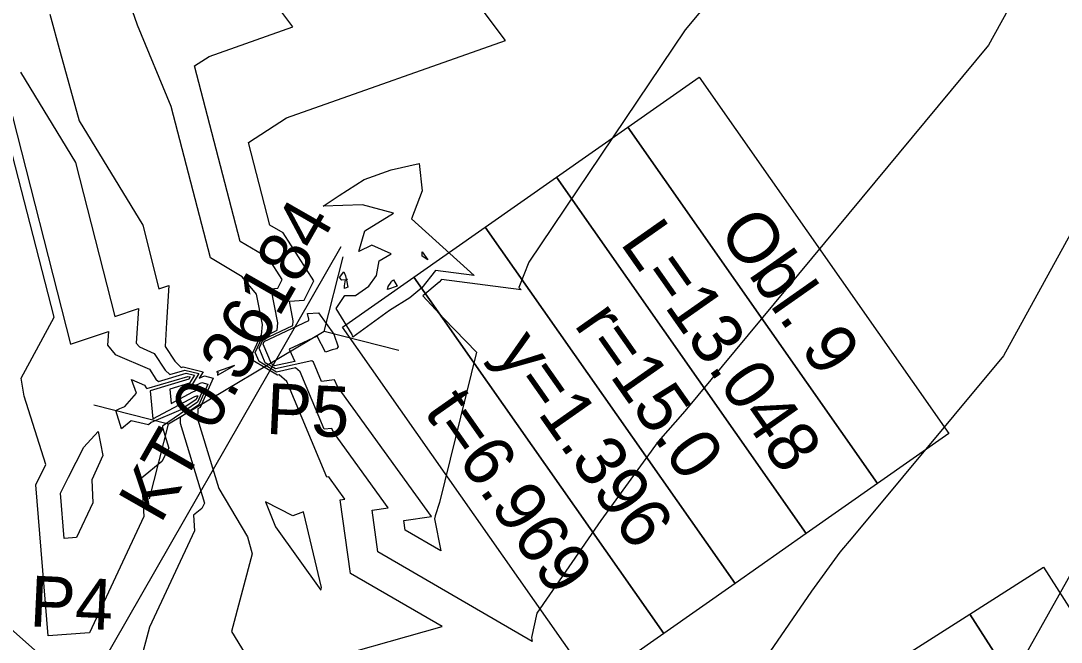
# Model space of a CAD drawing. Extents: x -549394 to -546608, y -1037055 to -1033629.
# Drawn here: x -547879.1 to -547807.4, y -1034621 to -1034578.2 of the extents above; entities that cross this region are included whole.
import ezdxf

# ---------------------------------------------------------------- set-up
doc = ezdxf.new("R2010")
doc.units = 0
for name, color, linetype in [('hlavni_vrst', 7, 'Continuous'), ('norm_vrst', 7, 'Continuous'), ('x_navrh_C21', 7, 'Continuous'), ('x_popis_C21', 7, 'Continuous'), ('x_popis_oblouky_C21', 7, 'Continuous')]:
    doc.layers.add(name, color=color, linetype=linetype)

msp = doc.modelspace()

# ---------------------------------------------------------------- linework, layer by layer
at = {"layer": 'hlavni_vrst'}
for p, q in [((-547853.521, -1034588.452), (-547851.595, -1034588.019)), ((-547851.595, -1034588.019), (-547851.381, -1034589.902)), ((-547855.388, -1034589.111), (-547853.521, -1034588.452)), ((-547857.107, -1034590.208), (-547855.388, -1034589.111)), ((-547851.381, -1034589.902), (-547852.13, -1034591.833)), ((-547858.221, -1034590.959), (-547857.107, -1034590.208)), ((-547855.504, -1034590.85), (-547858.221, -1034590.959)), ((-547853.377, -1034591.44), (-547855.504, -1034590.85)), ((-547855.351, -1034592.643), (-547853.377, -1034591.44)), ((-547852.13, -1034591.833), (-547847.809, -1034595.731)), ((-547855.762, -1034594.075), (-547855.351, -1034592.643)), ((-547854.855, -1034593.643), (-547855.762, -1034594.075)), ((-547853.538, -1034594.235), (-547854.855, -1034593.643)), ((-547854.347, -1034594.721), (-547853.538, -1034594.235)), ((-547854.55, -1034595.725), (-547854.347, -1034594.721)), ((-547857.092, -1034595.861), (-547856.786, -1034595.468)), ((-547856.931, -1034596.053), (-547857.092, -1034595.861)), ((-547856.786, -1034595.468), (-547856.667, -1034595.745)), ((-547856.667, -1034595.745), (-547856.633, -1034595.975)), ((-547855.075, -1034596.46), (-547854.55, -1034595.725)), ((-547850.462, -1034595.386), (-547851.426, -1034596.579)), ((-547847.809, -1034595.731), (-547850.462, -1034595.386)), ((-547856.673, -1034596.018), (-547856.931, -1034596.053)), ((-547856.75, -1034596.432), (-547856.673, -1034596.018)), ((-547856.746, -1034596.62), (-547856.75, -1034596.432)), ((-547856.509, -1034596.529), (-547856.746, -1034596.62)), ((-547856.633, -1034595.975), (-547856.54, -1034595.986)), ((-547856.54, -1034595.986), (-547856.614, -1034596.04)), ((-547856.614, -1034596.04), (-547856.509, -1034596.529)), ((-547855.994, -1034597.097), (-547855.075, -1034596.46)), ((-547851.426, -1034596.579), (-547852.253, -1034597.271)), ((-547857.314, -1034598.005), (-547856.711, -1034597.101)), ((-547856.711, -1034597.101), (-547855.994, -1034597.097)), ((-547852.253, -1034597.271), (-547853.651, -1034598.143)), ((-547856.224, -1034599.788), (-547857.314, -1034598.005)), ((-547859.286, -1034598.341), (-547858.543, -1034598.291)), ((-547859.207, -1034598.74), (-547859.286, -1034598.341)), ((-547859.213, -1034598.829), (-547859.207, -1034598.74)), ((-547858.543, -1034598.291), (-547857.475, -1034599.766)), ((-547853.651, -1034598.143), (-547856.17, -1034599.983)), ((-547862.271, -1034600.284), (-547859.213, -1034598.829)), ((-547858.617, -1034599.902), (-547860.547, -1034600.802)), ((-547858.049, -1034601.011), (-547858.617, -1034599.902)), ((-547857.475, -1034599.766), (-547857.184, -1034600.64)), ((-547856.17, -1034599.983), (-547856.224, -1034599.788)), ((-547862.351, -1034600.455), (-547862.271, -1034600.284)), ((-547861.768, -1034601.826), (-547862.351, -1034600.455)), ((-547860.547, -1034600.802), (-547860.166, -1034601.644)), ((-547857.601, -1034600.846), (-547858.049, -1034601.011)), ((-547857.301, -1034600.784), (-547857.601, -1034600.846)), ((-547857.184, -1034600.64), (-547857.301, -1034600.784)), ((-547860.166, -1034601.644), (-547861.563, -1034601.95)), ((-547861.563, -1034601.95), (-547861.768, -1034601.826)), ((-547871.413, -1034602.907), (-547870.531, -1034603.292)), ((-547871.075, -1034603.842), (-547871.413, -1034602.907)), ((-547870.361, -1034603.525), (-547867.543, -1034602.682)), ((-547867.477, -1034602.878), (-547870.144, -1034603.666)), ((-547867.543, -1034602.682), (-547867.381, -1034602.722)), ((-547867.381, -1034602.722), (-547867.477, -1034602.878)), ((-547870.531, -1034603.292), (-547870.41, -1034603.477)), ((-547870.41, -1034603.477), (-547870.361, -1034603.525)), ((-547870.144, -1034603.666), (-547869.953, -1034605.602)), ((-547871.871, -1034604.751), (-547871.075, -1034603.842)), ((-547869.953, -1034605.602), (-547867.058, -1034604.069)), ((-547866.966, -1034604.263), (-547868.016, -1034604.985)), ((-547867.058, -1034604.069), (-547866.93, -1034604.011)), ((-547866.862, -1034604.032), (-547866.966, -1034604.263)), ((-547866.93, -1034604.011), (-547866.862, -1034604.032)), ((-547872.506, -1034605.034), (-547872.225, -1034604.888)), ((-547872.106, -1034606.297), (-547872.506, -1034605.034)), ((-547872.225, -1034604.888), (-547871.871, -1034604.751)), ((-547868.016, -1034604.985), (-547870.056, -1034605.849)), ((-547871.445, -1034605.746), (-547872.106, -1034606.297)), ((-547870.259, -1034606.01), (-547871.445, -1034605.746)), ((-547870.056, -1034605.849), (-547870.259, -1034606.01)), ((-547874.719, -1034607.567), (-547873.72, -1034606.483)), ((-547873.72, -1034606.483), (-547873.397, -1034608.133)), ((-547875.771, -1034609.628), (-547874.719, -1034607.567)), ((-547873.397, -1034608.133), (-547874.166, -1034609.817)), ((-547876.314, -1034610.726), (-547875.771, -1034609.628)), ((-547874.166, -1034609.817), (-547874.076, -1034611.385)), ((-547876.056, -1034613.857), (-547876.314, -1034610.726)), ((-547874.076, -1034611.385), (-547875.202, -1034613.795)), ((-547875.202, -1034613.795), (-547876.056, -1034613.857))]:
    msp.add_line(p, q, dxfattribs=at)
at = {"layer": 'norm_vrst'}
for p, q in [((-547845.652, -1034579.544), (-547858.445, -1034562.366)), ((-547820.188, -1034563.233), (-547833.272, -1034578.787)), ((-547860.305, -1034578.591), (-547865.201, -1034572.017)), ((-547795.757, -1034572.882), (-547811.338, -1034601.266)), ((-547871.007, -1034578.468), (-547872.082, -1034575.43)), ((-547809.98, -1034575.524), (-547812.357, -1034579.854)), ((-547784.032, -1034575.823), (-547810.04, -1034622.26)), ((-547877.043, -1034577.709), (-547876.332, -1034580.334)), ((-547868.69, -1034584.087), (-547871.007, -1034578.468)), ((-547866.076, -1034580.629), (-547860.305, -1034578.591)), ((-547833.272, -1034578.787), (-547844.051, -1034594.817)), ((-547860.732, -1034584.87), (-547845.652, -1034579.544)), ((-547812.357, -1034579.854), (-547833.299, -1034605.077)), ((-547876.332, -1034580.334), (-547875.029, -1034585.079)), ((-547867.085, -1034581.273), (-547866.076, -1034580.629)), ((-547863.924, -1034593.382), (-547867.085, -1034581.273)), ((-547879.072, -1034581.725), (-547875.288, -1034587.935)), ((-547876.753, -1034598.603), (-547880.784, -1034582.969)), ((-547879.928, -1034583.603), (-547875.623, -1034600.454)), ((-547865.969, -1034594.51), (-547868.69, -1034584.087)), ((-547875.029, -1034585.079), (-547870.648, -1034592.267)), ((-547863.368, -1034586.552), (-547860.732, -1034584.87)), ((-547861.88, -1034592.254), (-547863.368, -1034586.552)), ((-547875.288, -1034587.935), (-547872.578, -1034598.545)), ((-547870.648, -1034592.267), (-547869.532, -1034596.636)), ((-547860.97, -1034592.799), (-547861.88, -1034592.254)), ((-547858.851, -1034596.095), (-547860.97, -1034592.799)), ((-547861.992, -1034594.54), (-547863.924, -1034593.382)), ((-547851.394, -1034594.105), (-547850.995, -1034594.651)), ((-547851.382, -1034594.386), (-547851.394, -1034594.105)), ((-547850.995, -1034594.651), (-547851.382, -1034594.386)), ((-547863.798, -1034595.811), (-547865.969, -1034594.51)), ((-547861.044, -1034596.015), (-547861.992, -1034594.54)), ((-547844.051, -1034594.817), (-547844.726, -1034596.561)), ((-547862.817, -1034597.017), (-547863.798, -1034595.811)), ((-547869.532, -1034596.636), (-547868.856, -1034596.414)), ((-547868.856, -1034596.414), (-547869.021, -1034598.962)), ((-547861.801, -1034596.639), (-547861.348, -1034596.609)), ((-547861.339, -1034598.983), (-547861.801, -1034596.639)), ((-547861.348, -1034596.609), (-547861.044, -1034596.015)), ((-547859.531, -1034597.422), (-547858.851, -1034596.095)), ((-547853.121, -1034596.464), (-547853.774, -1034596.684)), ((-547853.774, -1034596.684), (-547853.745, -1034596.495)), ((-547853.745, -1034596.495), (-547853.522, -1034596.183)), ((-547853.522, -1034596.183), (-547853.51, -1034596.126)), ((-547853.51, -1034596.126), (-547853.357, -1034596.034)), ((-547853.357, -1034596.034), (-547853.121, -1034596.464)), ((-547850.219, -1034596.185), (-547851.354, -1034597.135)), ((-547850.065, -1034595.994), (-547850.219, -1034596.185)), ((-547844.56, -1034596.711), (-547850.065, -1034595.994)), ((-547844.726, -1034596.561), (-547844.56, -1034596.711)), ((-547862.405, -1034599.104), (-547862.817, -1034597.017)), ((-547851.354, -1034597.135), (-547849.909, -1034598.682)), ((-547872.578, -1034598.545), (-547870.937, -1034598.005)), ((-547870.937, -1034598.005), (-547871.091, -1034600.383)), ((-547860.543, -1034597.49), (-547859.531, -1034597.422)), ((-547860.273, -1034598.861), (-547860.543, -1034597.49)), ((-547879.03, -1034602.798), (-547876.753, -1034598.603)), ((-547849.909, -1034598.682), (-547847.64, -1034601.011)), ((-547869.021, -1034598.962), (-547869.11, -1034600.611)), ((-547862.456, -1034599.843), (-547862.405, -1034599.104)), ((-547862.428, -1034600.006), (-547861.375, -1034599.505)), ((-547862.35, -1034600.145), (-547860.294, -1034599.167)), ((-547861.375, -1034599.505), (-547861.339, -1034598.983)), ((-547860.294, -1034599.167), (-547860.273, -1034598.861)), ((-547875.623, -1034600.454), (-547873.018, -1034599.596)), ((-547873.018, -1034599.596), (-547873.078, -1034600.533)), ((-547863.181, -1034601.314), (-547862.506, -1034599.867)), ((-547862.904, -1034601.027), (-547862.428, -1034600.006)), ((-547862.627, -1034600.741), (-547862.35, -1034600.145)), ((-547862.506, -1034599.867), (-547862.456, -1034599.843)), ((-547873.078, -1034600.533), (-547872.552, -1034601.163)), ((-547871.091, -1034600.383), (-547870.865, -1034600.653)), ((-547870.865, -1034600.653), (-547869.854, -1034601.094)), ((-547869.11, -1034600.611), (-547868.433, -1034601.639)), ((-547862.201, -1034601.744), (-547862.627, -1034600.741)), ((-547872.552, -1034601.163), (-547870.193, -1034602.193)), ((-547869.854, -1034601.094), (-547869.092, -1034602.251)), ((-547868.433, -1034601.639), (-547867.998, -1034602.063)), ((-547863.068, -1034601.579), (-547863.181, -1034601.314)), ((-547861.367, -1034602.608), (-547863.068, -1034601.579)), ((-547862.635, -1034601.662), (-547862.904, -1034601.027)), ((-547861.432, -1034602.389), (-547862.635, -1034601.662)), ((-547858.993, -1034601.62), (-547861.498, -1034602.169)), ((-547858.887, -1034601.709), (-547858.993, -1034601.62)), ((-547847.64, -1034601.011), (-547850.189, -1034611.368)), ((-547811.338, -1034601.266), (-547821.703, -1034613.75)), ((-547870.193, -1034602.193), (-547869.751, -1034602.864)), ((-547869.092, -1034602.251), (-547868.786, -1034602.55)), ((-547868.786, -1034602.55), (-547867.757, -1034602.243)), ((-547867.998, -1034602.063), (-547867.864, -1034602.023)), ((-547867.864, -1034602.023), (-547866.488, -1034602.365)), ((-547867.757, -1034602.243), (-547866.786, -1034602.484)), ((-547866.488, -1034602.365), (-547866.757, -1034602.8)), ((-547864.326, -1034601.926), (-547865.567, -1034602.37)), ((-547865.567, -1034602.37), (-547865.444, -1034602.406)), ((-547865.491, -1034602.603), (-547864.326, -1034601.926)), ((-547861.498, -1034602.169), (-547862.201, -1034601.744)), ((-547860.12, -1034602.101), (-547861.432, -1034602.389)), ((-547859.802, -1034602.366), (-547860.12, -1034602.101)), ((-547858.155, -1034606.326), (-547859.802, -1034602.366)), ((-547858.338, -1034603.029), (-547858.887, -1034601.709)), ((-547878.824, -1034604.043), (-547879.03, -1034602.798)), ((-547869.751, -1034602.864), (-547869.573, -1034603.038)), ((-547869.573, -1034603.038), (-547867.65, -1034602.462)), ((-547867.65, -1034602.462), (-547867.083, -1034602.603)), ((-547867.083, -1034602.603), (-547867.42, -1034603.147)), ((-547866.786, -1034602.484), (-547867.363, -1034603.417)), ((-547867.353, -1034603.446), (-547866.572, -1034603.095)), ((-547866.757, -1034602.8), (-547866.393, -1034602.637)), ((-547865.799, -1034602.813), (-547866.701, -1034604.826)), ((-547866.572, -1034603.095), (-547866.153, -1034603.219)), ((-547866.393, -1034602.637), (-547865.799, -1034602.813)), ((-547865.485, -1034602.498), (-547865.491, -1034602.603)), ((-547865.444, -1034602.406), (-547865.485, -1034602.498)), ((-547861.247, -1034602.582), (-547861.367, -1034602.608)), ((-547860.716, -1034603.024), (-547861.247, -1034602.582)), ((-547857.972, -1034609.624), (-547860.716, -1034603.024)), ((-547857.428, -1034602.925), (-547858.338, -1034603.029)), ((-547857.222, -1034603.368), (-547857.428, -1034602.925)), ((-547867.42, -1034603.147), (-547868.786, -1034603.551)), ((-547868.786, -1034603.551), (-547868.688, -1034604.542)), ((-547868.688, -1034604.542), (-547867.205, -1034603.757)), ((-547867.363, -1034603.417), (-547867.428, -1034603.436)), ((-547867.428, -1034603.436), (-547867.423, -1034603.483)), ((-547867.423, -1034603.483), (-547867.353, -1034603.446)), ((-547867.205, -1034603.757), (-547866.751, -1034603.553)), ((-547866.507, -1034603.625), (-547866.878, -1034604.451)), ((-547866.153, -1034603.219), (-547866.79, -1034604.638)), ((-547866.751, -1034603.553), (-547866.507, -1034603.625)), ((-547850.74, -1034612.328), (-547857.222, -1034603.368)), ((-547877.329, -1034608.761), (-547878.824, -1034604.043)), ((-547866.878, -1034604.451), (-547869.284, -1034606.104)), ((-547866.79, -1034604.638), (-547868.066, -1034605.515)), ((-547866.848, -1034604.927), (-547866.867, -1034605.616)), ((-547866.701, -1034604.826), (-547866.848, -1034604.927)), ((-547833.299, -1034605.077), (-547835.136, -1034607.175)), ((-547868.066, -1034605.515), (-547868.077, -1034605.911)), ((-547868.077, -1034605.911), (-547866.388, -1034611.423)), ((-547866.867, -1034605.616), (-547865.396, -1034610.418)), ((-547869.284, -1034606.104), (-547869.287, -1034606.207)), ((-547869.287, -1034606.207), (-547868.849, -1034607.635)), ((-547857.626, -1034606.266), (-547858.155, -1034606.326)), ((-547857.506, -1034606.523), (-547857.626, -1034606.266)), ((-547853.736, -1034611.735), (-547857.506, -1034606.523)), ((-547835.136, -1034607.175), (-547839.083, -1034612.606)), ((-547868.849, -1034607.635), (-547869.342, -1034608.558)), ((-547878.021, -1034610.16), (-547877.329, -1034608.761)), ((-547869.342, -1034608.558), (-547870.732, -1034609.7)), ((-547877.163, -1034620.571), (-547878.021, -1034610.16)), ((-547870.732, -1034609.7), (-547870.58, -1034612.349)), ((-547857.823, -1034609.607), (-547857.972, -1034609.624)), ((-547857.789, -1034609.679), (-547857.823, -1034609.607)), ((-547856.732, -1034611.141), (-547857.789, -1034609.679)), ((-547865.396, -1034610.418), (-547863.429, -1034613.728)), ((-547866.388, -1034611.423), (-547866.586, -1034611.793)), ((-547860.294, -1034612.303), (-547862.189, -1034611.325)), ((-547862.189, -1034611.325), (-547861.502, -1034613.044)), ((-547857.043, -1034611.187), (-547856.732, -1034611.141)), ((-547856.324, -1034616.26), (-547857.043, -1034611.187)), ((-547850.189, -1034611.368), (-547850.497, -1034612.281)), ((-547870.58, -1034612.349), (-547874.323, -1034620.366)), ((-547866.586, -1034611.793), (-547867.144, -1034612.251)), ((-547867.144, -1034612.251), (-547867.083, -1034613.314)), ((-547859.573, -1034612.021), (-547860.294, -1034612.303)), ((-547859.552, -1034612.097), (-547859.573, -1034612.021)), ((-547858.331, -1034617.24), (-547859.552, -1034612.097)), ((-547854.846, -1034611.897), (-547853.736, -1034611.735)), ((-547854.44, -1034614.764), (-547854.846, -1034611.897)), ((-547852.649, -1034612.607), (-547850.74, -1034612.328)), ((-547850.497, -1034612.281), (-547850.546, -1034612.503)), ((-547861.502, -1034613.044), (-547858.385, -1034617.413)), ((-547852.555, -1034613.269), (-547852.649, -1034612.607)), ((-547850.546, -1034612.503), (-547850.1, -1034614.695)), ((-547839.083, -1034612.606), (-547843.485, -1034619.005)), ((-547867.083, -1034613.314), (-547870.184, -1034619.954)), ((-547863.429, -1034613.728), (-547863.103, -1034614.905)), ((-547850.1, -1034614.695), (-547852.555, -1034613.269)), ((-547821.703, -1034613.75), (-547822.613, -1034614.789)), ((-547863.103, -1034614.905), (-547864.54, -1034620.272)), ((-547843.802, -1034620.945), (-547854.44, -1034614.764)), ((-547822.613, -1034614.789), (-547824.566, -1034617.477)), ((-547850.018, -1034619.923), (-547856.324, -1034616.26)), ((-547858.385, -1034617.413), (-547858.331, -1034617.24)), ((-547824.566, -1034617.477), (-547827.692, -1034622.021)), ((-547843.485, -1034619.005), (-547843.857, -1034620.676)), ((-547870.184, -1034619.954), (-547870.954, -1034622.829)), ((-547864.54, -1034620.272), (-547862.569, -1034623.454)), ((-547862.569, -1034623.454), (-547850.018, -1034619.923)), ((-547874.323, -1034620.366), (-547877.163, -1034620.571)), ((-547843.857, -1034620.676), (-547843.802, -1034620.945))]:
    msp.add_line(p, q, dxfattribs=at)
at = {"layer": 'x_navrh_C21'}
msp.add_line((-547880.147, -1034619.702), (-547874.549, -1034624.679), dxfattribs=at)
for points in [[(-547852.998, -1034600.895), (-547858.138, -1034599.589), (-547856.832, -1034594.449)], [(-547858.138, -1034599.589), (-547868.882, -1034605.979)], [(-547870.188, -1034611.119), (-547868.882, -1034605.979), (-547874.022, -1034604.673)]]:
    msp.add_lwpolyline(points, dxfattribs=at)
at = {"layer": 'x_popis_oblouky_C21'}
for points in [[(-547832.314, -1034582.06), (-547815.093, -1034606.625), (-547820.006, -1034610.07), (-547837.227, -1034585.505)], [(-547837.227, -1034585.505), (-547820.006, -1034610.07), (-547824.919, -1034613.514), (-547842.14, -1034588.949)], [(-547842.14, -1034588.949), (-547824.919, -1034613.514), (-547829.832, -1034616.958), (-547847.053, -1034592.393)], [(-547847.053, -1034592.393), (-547829.832, -1034616.958), (-547834.745, -1034620.402), (-547851.966, -1034595.837)], [(-547851.966, -1034595.837), (-547834.745, -1034620.402), (-547839.658, -1034623.846), (-547856.879, -1034599.281)], [(-547808.585, -1034615.826), (-547792.422, -1034641.1), (-547797.477, -1034644.332), (-547813.639, -1034619.058)], [(-547813.639, -1034619.058), (-547797.477, -1034644.332), (-547802.532, -1034647.565), (-547818.694, -1034622.291)]]:
    msp.add_lwpolyline(points, close=True, dxfattribs=at)
msp.add_lwpolyline([(-547857.006, -1034593.764), (-547875.675, -1034626.326)], dxfattribs=at)

# ---------------------------------------------------------------- texts
at = {"layer": 'x_popis_C21'}
for s, p in [('P5', (-547862.201, -1034606.634)), ('P4', (-547878.483, -1034619.901))]:
    msp.add_text(s, height=3.5, rotation=357.3209, dxfattribs=at).set_placement(p)
at = {"layer": 'x_popis_oblouky_C21'}
for s, rotation, p in [('KT 0.36184', 60.17368, (-547869.426, -1034612.909)), ('Obl. 9', 305.05352, (-547831.05, -1034592.668)), ('L=13.048', 305.05352, (-547837.804, -1034593.488)), ('r=15.0', 305.05352, (-547840.97, -1034599.124)), ('y=1.396', 305.05352, (-547846.392, -1034601.074)), ('t=6.969', 305.05352, (-547851.325, -1034605.102))]:
    msp.add_text(s, height=3.5, rotation=rotation, dxfattribs=at).set_placement(p)

doc.saveas('drawing.dxf')
